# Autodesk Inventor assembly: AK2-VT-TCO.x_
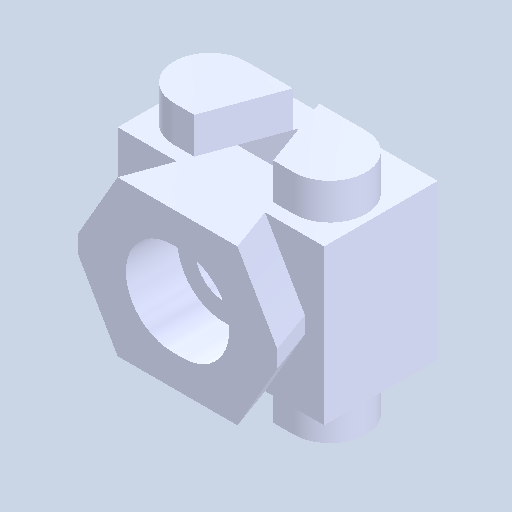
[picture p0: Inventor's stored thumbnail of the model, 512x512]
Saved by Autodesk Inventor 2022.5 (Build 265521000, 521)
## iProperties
Created: 2024-07
Part Number: AK2-VT-TCO.x_
Document SubType Name: Assembly
Designer: ImaoCorp
Author: ImaoCorp
Sending System: SOLIDWORKS 2022-2022290
MC: AMD64
MC_MODEL: Intel64 Family 6 Model 60 Stepping 3, GenuineIntel
OS: Windows_NT
FRU: Parasolid Version 33.1, build 260,  4-25-2022
FORMAT: text
GUISE: transmit
KEY: FILEAK2-VT-TCO.x_t
DATE: Mon Jul  1 10:06:50 2024
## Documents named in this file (4)
- X:\14_SW2022-Inv2022\07_2024-10新製品(WHS)\OKV_データ\a\ak2-vt-tco\AK2-VT-TCO.x_.iam
- X:\14_SW2022-Inv2022\07_2024-10新製品(WHS)\OKV_データ\a\ak2-vt-tco\AK2-VT-TCO_01.ipt
- X:\14_SW2022-Inv2022\07_2024-10新製品(WHS)\OKV_データ\a\ak2-vt-tco\AK2-VT-TCO_02.ipt
- X:\14_SW2022-Inv2022\07_2024-10新製品(WHS)\OKV_データ\a\ak2-vt-tco\AK2-VT-TCO_03.ipt
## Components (3 placed, 3 different names)
1. AK2-VT-TCO_01
2. AK2-VT-TCO_02
3. AK2-VT-TCO_03
